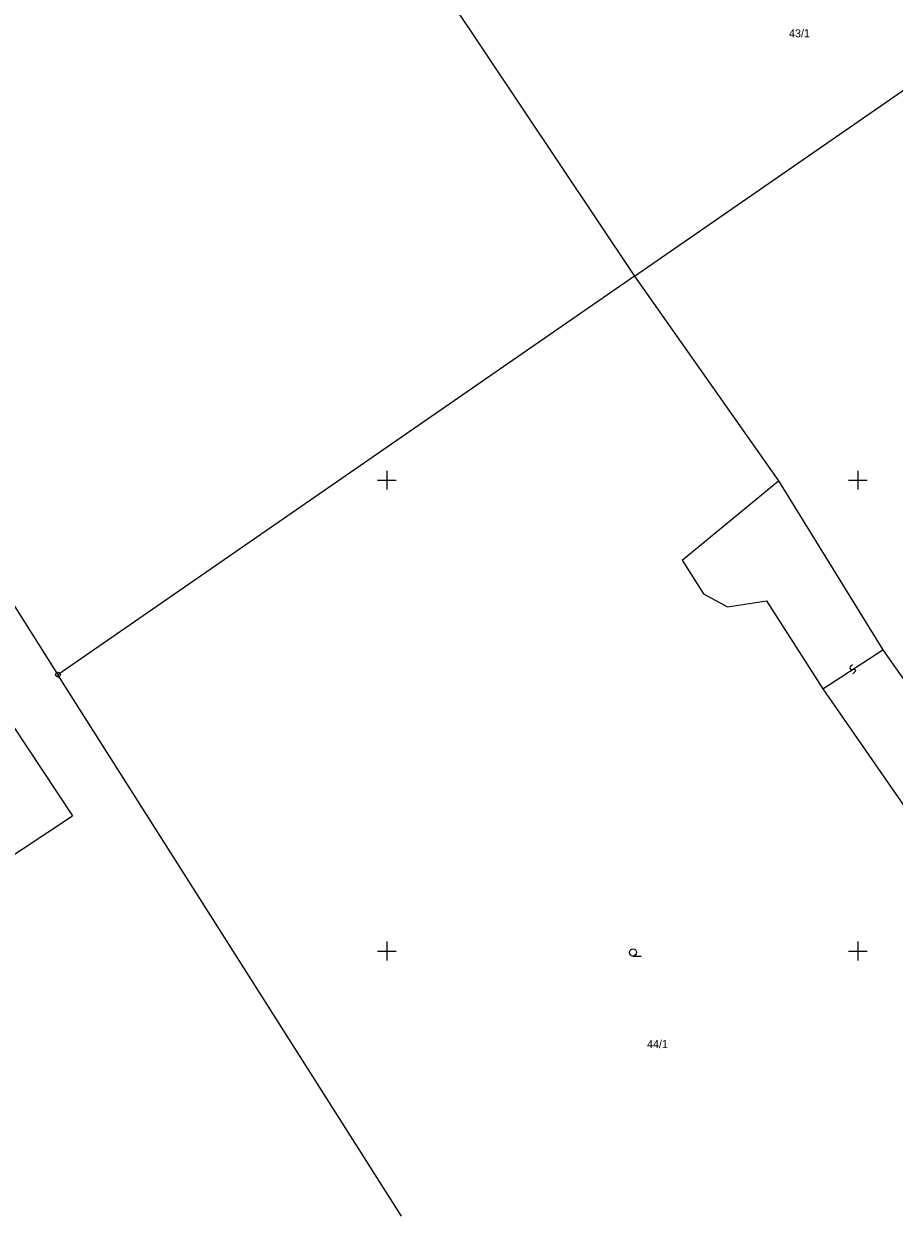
# Model space of a CAD drawing. Extents: x -492811 to -492366, y -1127107 to -1126748.
# Drawn here: x -492755.4 to -492718.5, y -1127091.3 to -1127040.6 of the extents above; entities that cross this region are included whole.
import ezdxf

# ---------------------------------------------------------------- set-up
doc = ezdxf.new("R2010")
doc.units = 0
doc.layers.add('katastrální mapa', color=7, linetype='Continuous')
doc.layers.add('síť', color=7, linetype='Continuous')

msp = doc.modelspace()

# ---------------------------------------------------------------- linework, layer by layer
at = {"layer": 'katastrální mapa'}
for p, q in [((-492729.49, -1127051.33), (-492701.56, -1127032.01)), ((-492739.95, -1127035.67), (-492729.49, -1127051.33)), ((-492729.49, -1127051.33), (-492753.97, -1127068.26)), ((-492729.49, -1127051.33), (-492723.37, -1127060.03)), ((-492762.51, -1127054.81), (-492753.97, -1127068.26)), ((-492765.13, -1127056.52), (-492753.35, -1127074.26)), ((-492727.46, -1127063.4), (-492723.37, -1127060.03)), ((-492723.37, -1127060.03), (-492718.94, -1127067.2)), ((-492727.46, -1127063.4), (-492726.55, -1127064.83)), ((-492726.55, -1127064.83), (-492725.54, -1127065.38)), ((-492725.54, -1127065.38), (-492723.88, -1127065.13)), ((-492723.88, -1127065.13), (-492721.49, -1127068.86)), ((-492721.49, -1127068.86), (-492718.94, -1127067.2)), ((-492718.94, -1127067.2), (-492714.3, -1127073.82)), ((-492720.32, -1127067.93), (-492720.34, -1127067.99)), ((-492720.34, -1127067.99), (-492720.31, -1127068.02)), ((-492720.22, -1127067.84), (-492720.32, -1127067.93)), ((-492720.31, -1127068.02), (-492720.26, -1127068.04)), ((-492720.26, -1127068.04), (-492720.17, -1127068.02)), ((-492720.17, -1127068.02), (-492720.12, -1127068.04)), ((-492720.12, -1127068.04), (-492720.09, -1127068.07)), ((-492739.38, -1127091.26), (-492753.97, -1127068.26)), ((-492720.11, -1127068.13), (-492720.21, -1127068.22)), ((-492720.09, -1127068.07), (-492720.11, -1127068.13)), ((-492721.49, -1127068.86), (-492716.87, -1127075.52)), ((-492765.29, -1127082.14), (-492753.35, -1127074.26)), ((-492729.55, -1127080.21), (-492729.2, -1127080.21))]:
    msp.add_line(p, q, dxfattribs=at)
for centre, radius in [((-492753.97, -1127068.26), 0.1), ((-492753.97, -1127068.26), 0.002), ((-492729.55, -1127080.06), 0.15)]:
    msp.add_circle(centre, radius, dxfattribs=at)
at = {"layer": 'síť'}
for p, q in [((-492740, -1127059.6), (-492740, -1127060.4)), ((-492720, -1127059.6), (-492720, -1127060.4)), ((-492740.4, -1127060), (-492739.6, -1127060)), ((-492720.4, -1127060), (-492719.6, -1127060)), ((-492740, -1127079.6), (-492740, -1127080.4)), ((-492720, -1127079.6), (-492720, -1127080.4)), ((-492740.4, -1127080), (-492739.6, -1127080)), ((-492720.4, -1127080), (-492719.6, -1127080))]:
    msp.add_line(p, q, dxfattribs=at)

# ---------------------------------------------------------------- texts
at = {"layer": 'katastrální mapa'}
for s, p in [('43/1', (-492722.92, -1127041.19)), ('44/1', (-492728.95, -1127084.12))]:
    msp.add_text(s, height=0.34, dxfattribs=at).set_placement(p)

doc.saveas('drawing.dxf')
